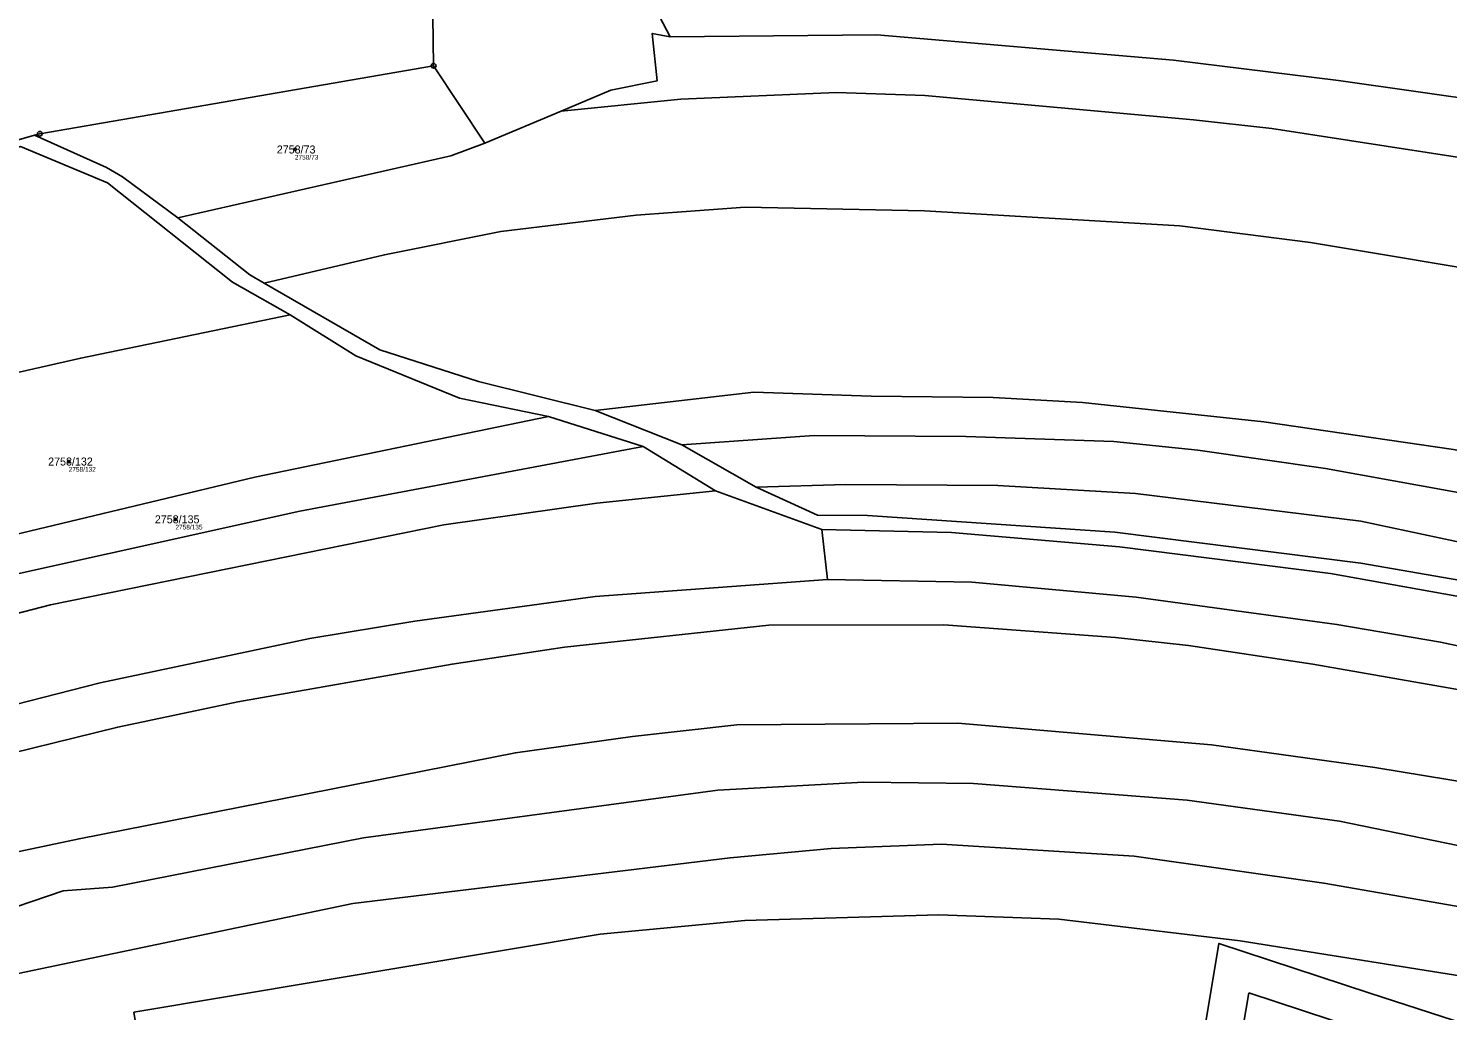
# Model space of a CAD drawing. Extents: x -739214 to -733252, y -1147612 to -1142842.
# Drawn here: x -738866.3 to -738564.8, y -1144790.3 to -1144581.7 of the extents above; entities that cross this region are included whole.
import ezdxf

# ---------------------------------------------------------------- set-up
doc = ezdxf.new("R2010")
doc.units = 0
for name, color, linetype in [('Definiční body', 7, 'Continuous'), ('Hranice parcel', 7, 'Continuous'), ('Parcelní čísla', 7, 'Continuous'), ('Polygon ku', 7, 'Continuous'), ('Polygon parcely', 7, 'Continuous'), ('Věcná břemena k části', 7, 'Continuous'), ('Značky bodu BP', 7, 'Continuous')]:
    doc.layers.add(name, color=color, linetype=linetype)

msp = doc.modelspace()

# ---------------------------------------------------------------- linework, layer by layer
at = {"layer": 'Definiční body'}
for centre in [(-738809.72, -1144607.42), (-738857.77, -1144673.7), (-738835.1, -1144685.97)]:
    msp.add_circle(centre, 0.25, dxfattribs=at)
at = {"layer": 'Hranice parcel'}
for p, q in [((-738780.23, -1144589.65), (-738863.93, -1144604.08)), ((-738769.34, -1144606.08), (-738780.23, -1144589.65)), ((-738769.34, -1144606.08), (-738753.15, -1144599.26)), ((-738863.93, -1144604.08), (-738865.07, -1144604.41)), ((-738755.81, -1144664.17), (-738735.7, -1144670.49)), ((-738727.49, -1144670.14), (-738745.92, -1144662.85)), ((-738735.7, -1144670.49), (-738720.33, -1144679.94)), ((-738711.74, -1144679.15), (-738727.49, -1144670.14)), ((-738720.33, -1144679.94), (-738697.72, -1144688.15)), ((-738697.72, -1144688.15), (-738696.55, -1144698.78))]:
    msp.add_line(p, q, dxfattribs=at)
for points in [[(-738777.14, -1144551.06), (-738777.95, -1144556.74), (-738780.47, -1144573.76), (-738780.23, -1144589.65)], [(-738729.99, -1144583.51), (-738736.86, -1144570.33), (-738742.47, -1144558.02)], [(-738753.15, -1144599.26), (-738742.61, -1144594.82), (-738732.73, -1144592.83), (-738733.79, -1144582.76), (-738729.99, -1144583.51)], [(-738729.99, -1144583.51), (-738686.04, -1144583.08), (-738623, -1144588.46), (-738587.96, -1144592.8), (-738539.21, -1144599.7), (-738494.01, -1144607.59), (-738447.81, -1144618.01), (-738328.4, -1144646.66)], [(-738753.15, -1144599.26), (-738727.73, -1144596.76), (-738694.67, -1144595.34), (-738675.84, -1144595.98), (-738618.78, -1144601.09), (-738602.14, -1144602.93), (-738520.52, -1144615.55), (-738463.61, -1144627.54), (-738400.53, -1144642.44), (-738380.67, -1144646.44), (-738343.35, -1144655.44), (-738326.71, -1144658.87), (-738285.33, -1144666.02)], [(-738865.07, -1144604.41), (-738883.19, -1144609.6), (-738884.82, -1144610.47)], [(-738865.07, -1144604.41), (-738849.74, -1144611.23), (-738846.34, -1144613.24), (-738834.59, -1144621.96)], [(-738884.82, -1144610.47), (-738884.36, -1144611.58), (-738868.01, -1144606.82), (-738849.51, -1144614.5), (-738822.95, -1144635.62), (-738810.74, -1144642.56)], [(-738834.59, -1144621.96), (-738776.55, -1144608.79), (-738769.34, -1144606.08)], [(-738816.27, -1144635.82), (-738790.71, -1144629.78), (-738765.96, -1144624.84), (-738737.19, -1144621.35), (-738714.05, -1144619.69), (-738675.95, -1144620.48), (-738621.71, -1144623.66), (-738593.96, -1144627.15), (-738549.36, -1144634.62), (-738467.05, -1144650.77), (-738381.69, -1144670.37), (-738342.61, -1144677.12), (-738282.28, -1144686.41)], [(-738816.27, -1144635.82), (-738819.32, -1144634.07), (-738834.59, -1144621.96)], [(-738745.92, -1144662.85), (-738770.72, -1144656.73), (-738791.64, -1144649.96), (-738816.27, -1144635.82)], [(-738931.09, -1144668.92), (-738855.23, -1144651.72), (-738810.74, -1144642.56)], [(-738810.74, -1144642.56), (-738796.79, -1144651.27), (-738774.75, -1144660.26), (-738755.81, -1144664.17)], [(-738745.92, -1144662.85), (-738712.17, -1144659), (-738687.27, -1144659.79), (-738661.34, -1144660.12), (-738642.34, -1144661.13), (-738603.83, -1144665.27), (-738563.52, -1144671.15), (-738498, -1144684.06), (-738408.41, -1144703.91), (-738331.12, -1144719.75), (-738279.96, -1144728.46)], [(-738926.48, -1144701.79), (-738906.96, -1144698.24), (-738818.25, -1144677.05), (-738755.81, -1144664.17)], [(-738932.3, -1144703.13), (-738929.68, -1144712.57), (-738889.74, -1144702.21), (-738808.63, -1144684.22), (-738735.7, -1144670.49)], [(-738727.49, -1144670.14), (-738699.4, -1144668.15), (-738667.17, -1144668.37), (-738635.72, -1144669.48), (-738617.89, -1144671.27), (-738590.77, -1144675.16), (-738513.58, -1144689.15), (-738489.83, -1144694.47), (-738438.07, -1144706.79), (-738367.67, -1144721.57), (-738324.91, -1144729.9), (-738281.12, -1144737.92)], [(-739043.64, -1144738.41), (-739021.43, -1144737.54), (-739007.09, -1144735.54), (-738953.36, -1144724.86), (-738895.09, -1144712.74), (-738861.64, -1144704.16), (-738778.06, -1144687.15), (-738745.57, -1144682.54), (-738720.33, -1144679.94)], [(-738711.74, -1144679.15), (-738692.62, -1144678.6), (-738660.39, -1144678.82), (-738631.09, -1144680.49), (-738583.23, -1144686.39), (-738553.27, -1144692.71), (-738520.04, -1144698.71), (-738490.17, -1144704.7), (-738455.52, -1144712.8), (-738414.76, -1144721.93), (-738337.79, -1144737.47), (-738279.92, -1144748.35)], [(-738279.52, -1144758.68), (-738351.8, -1144744.67), (-738450.9, -1144722.85), (-738550.14, -1144701.05), (-738583.22, -1144695.29), (-738635.53, -1144688.73), (-738688.08, -1144685.17), (-738698.64, -1144685.06), (-738711.74, -1144679.15)], [(-738697.72, -1144688.15), (-738670.21, -1144688.75), (-738634.48, -1144691.79), (-738589.69, -1144697.46), (-738544.27, -1144705.61), (-738466.25, -1144723.6), (-738349.01, -1144748.05), (-738333.43, -1144752.01), (-738310.86, -1144756.48), (-738252.1, -1144766.82), (-738206.57, -1144771.52)], [(-738696.55, -1144698.78), (-738745.92, -1144702.39), (-738784.25, -1144707.6), (-738806.51, -1144711.26), (-738851.06, -1144720.74), (-738905.38, -1144734.58), (-738937.68, -1144741.77), (-738989.45, -1144749.94), (-739014.42, -1144755.11), (-739040.71, -1144758.17), (-739064.7, -1144758.63), (-739078.94, -1144757.8), (-739119.14, -1144754.37), (-739143.46, -1144751.76), (-739171.7, -1144747.33)], [(-738696.55, -1144698.78), (-738665.86, -1144699.31), (-738630.96, -1144702.5), (-738588.32, -1144708.29), (-738566.34, -1144712.1), (-738390.66, -1144749.52), (-738318.89, -1144764.13), (-738258.51, -1144774.18), (-738205.92, -1144778.86)], [(-739183.38, -1144756.59), (-739140.87, -1144761.52), (-739094.29, -1144766.15), (-739069.06, -1144767.9), (-739029.63, -1144766.65), (-739012.13, -1144765.04), (-738992.25, -1144760.79), (-738928.27, -1144750.02), (-738847.34, -1144730.12), (-738821.85, -1144724.75), (-738776.3, -1144716.74), (-738752.44, -1144713.11), (-738709, -1144708.48), (-738671.85, -1144708.36), (-738635.33, -1144711.11), (-738619.83, -1144712.74), (-738593.44, -1144716.74), (-738533.1, -1144727.26), (-738443.78, -1144747.77), (-738301.16, -1144775.3), (-738253.9, -1144782.41), (-738204.81, -1144786.85)], [(-739191.93, -1144773.83), (-739136.09, -1144782.62), (-739109.71, -1144785.29), (-739061.67, -1144788.4), (-739035.56, -1144788.05), (-739022.38, -1144787.2), (-738997.38, -1144783.49), (-738951.57, -1144774.09), (-738855.58, -1144753.81), (-738762.86, -1144735.55), (-738738.01, -1144732.08), (-738715.84, -1144729.62), (-738668.84, -1144729.28), (-738614.93, -1144733.9), (-738580.25, -1144738.68), (-738543.66, -1144744.74), (-738483.58, -1144758.77), (-738436.23, -1144768.97), (-738312.61, -1144792.56), (-738198.03, -1144807.72)], [(-739018.23, -1144795.76), (-739001.32, -1144795.15), (-738980.04, -1144791.01), (-738946.98, -1144785.78), (-738875.63, -1144770.55), (-738858.94, -1144764.88), (-738848.45, -1144764.09), (-738795.15, -1144753.65), (-738719.87, -1144743.52), (-738688.88, -1144741.81), (-738665.51, -1144742.12), (-738620.15, -1144745.66), (-738587.73, -1144750.11), (-738403.83, -1144787.9), (-738312.38, -1144804.82), (-738231.13, -1144815.26), (-738195.33, -1144820.56)], [(-739004.88, -1144809.81), (-738937.47, -1144798.69), (-738869.85, -1144782.72), (-738797.38, -1144767.56), (-738717.25, -1144757.85), (-738695.76, -1144755.92), (-738672.31, -1144754.96), (-738631.42, -1144757.49), (-738591.08, -1144763.25), (-738558.06, -1144769.02), (-738499.4, -1144781.27), (-738429.11, -1144797.13), (-738347.02, -1144813.34), (-738244.65, -1144832.1), (-738220.72, -1144837.15)], [(-739010.95, -1144831.34), (-738983.69, -1144828.66), (-738842.39, -1144800.36), (-738843.93, -1144790.67), (-738744.85, -1144774.09), (-738714.09, -1144771.16), (-738672.93, -1144769.95), (-738647.4, -1144770.87), (-738608.88, -1144775.47), (-738559.97, -1144783.32), (-738403.07, -1144818.2), (-738275.19, -1144842.8), (-738222.95, -1144854.1)]]:
    msp.add_lwpolyline(points, dxfattribs=at)
at = {"layer": 'Polygon ku'}
msp.add_lwpolyline([(-738782.62, -1144314.52), (-738764.08, -1144360.02), (-738761.91, -1144378.7), (-738761.22, -1144384.64), (-738769.11, -1144488.57), (-738770.19, -1144501.07), (-738770.52, -1144504.83), (-738777.14, -1144551.06), (-738777.95, -1144556.74), (-738780.47, -1144573.76), (-738780.23, -1144589.65), (-738863.93, -1144604.08), (-738865.07, -1144604.41), (-738883.19, -1144609.6)], dxfattribs=at)
at = {"layer": 'Polygon parcely'}
for points in [[(-738475.09, -1144582.57), (-738550.29, -1144563.03), (-738567.46, -1144567.5), (-738568.5, -1144579.44), (-738625.48, -1144569.7), (-738634.18, -1144556.85), (-738643.91, -1144551.66), (-738653.78, -1144541.27), (-738753.45, -1144529.96), (-738751.26, -1144537.68), (-738742.47, -1144558.02), (-738736.86, -1144570.33), (-738729.99, -1144583.51), (-738686.04, -1144583.08), (-738623, -1144588.46), (-738587.96, -1144592.8), (-738539.21, -1144599.7), (-738494.01, -1144607.59), (-738447.81, -1144618.01), (-738328.4, -1144646.66), (-738337.91, -1144625.79), (-738395.95, -1144612.45), (-738404.05, -1144599.36)], [(-738729.99, -1144583.51), (-738736.86, -1144570.33), (-738742.47, -1144558.02), (-738777.14, -1144551.06), (-738777.95, -1144556.74), (-738780.47, -1144573.76), (-738780.23, -1144589.65), (-738769.34, -1144606.08), (-738753.15, -1144599.26), (-738742.61, -1144594.82), (-738732.73, -1144592.83), (-738733.79, -1144582.76)], [(-738834.59, -1144621.96), (-738776.55, -1144608.79), (-738769.34, -1144606.08), (-738780.23, -1144589.65), (-738863.93, -1144604.08), (-738865.07, -1144604.41), (-738849.74, -1144611.23), (-738846.34, -1144613.24)], [(-738931.09, -1144668.92), (-738855.23, -1144651.72), (-738810.74, -1144642.56), (-738822.95, -1144635.62), (-738849.51, -1144614.5), (-738868.01, -1144606.82), (-738884.36, -1144611.58), (-738884.82, -1144610.47), (-738920.58, -1144629.59), (-738941.79, -1144651.66), (-738967.26, -1144676.45)], [(-738926.48, -1144701.79), (-738906.96, -1144698.24), (-738818.25, -1144677.05), (-738755.81, -1144664.17), (-738774.75, -1144660.26), (-738796.79, -1144651.27), (-738810.74, -1144642.56), (-738855.23, -1144651.72), (-738931.09, -1144668.92), (-738929.55, -1144677.06), (-738928.17, -1144695.03)], [(-738281.12, -1144737.92), (-738279.96, -1144728.46), (-738331.12, -1144719.75), (-738408.41, -1144703.91), (-738498, -1144684.06), (-738563.52, -1144671.15), (-738603.83, -1144665.27), (-738642.34, -1144661.13), (-738661.34, -1144660.12), (-738687.27, -1144659.79), (-738712.17, -1144659), (-738745.92, -1144662.85), (-738727.49, -1144670.14), (-738699.4, -1144668.15), (-738667.17, -1144668.37), (-738635.72, -1144669.48), (-738617.89, -1144671.27), (-738590.77, -1144675.16), (-738513.58, -1144689.15), (-738489.83, -1144694.47), (-738438.07, -1144706.79), (-738367.67, -1144721.57), (-738324.91, -1144729.9)], [(-738889.74, -1144702.21), (-738808.63, -1144684.22), (-738735.7, -1144670.49), (-738755.81, -1144664.17), (-738818.25, -1144677.05), (-738906.96, -1144698.24), (-738926.48, -1144701.79), (-738932.3, -1144703.13), (-738929.68, -1144712.57)], [(-739021.43, -1144737.54), (-739007.09, -1144735.54), (-738953.36, -1144724.86), (-738895.09, -1144712.74), (-738861.64, -1144704.16), (-738778.06, -1144687.15), (-738745.57, -1144682.54), (-738720.33, -1144679.94), (-738735.7, -1144670.49), (-738808.63, -1144684.22), (-738889.74, -1144702.21), (-738929.68, -1144712.57), (-738932.3, -1144703.13), (-738975.23, -1144713.01), (-739014.09, -1144719.06), (-739014.33, -1144725.67), (-739043.39, -1144730.93), (-739043.64, -1144738.41)], [(-738660.39, -1144678.82), (-738631.09, -1144680.49), (-738583.23, -1144686.39), (-738553.27, -1144692.71), (-738520.04, -1144698.71), (-738490.17, -1144704.7), (-738455.52, -1144712.8), (-738414.76, -1144721.93), (-738337.79, -1144737.47), (-738279.92, -1144748.35), (-738281.12, -1144737.92), (-738324.91, -1144729.9), (-738367.67, -1144721.57), (-738438.07, -1144706.79), (-738489.83, -1144694.47), (-738513.58, -1144689.15), (-738590.77, -1144675.16), (-738617.89, -1144671.27), (-738635.72, -1144669.48), (-738667.17, -1144668.37), (-738699.4, -1144668.15), (-738727.49, -1144670.14), (-738711.74, -1144679.15), (-738692.62, -1144678.6)], [(-738711.74, -1144679.15), (-738698.64, -1144685.06), (-738688.08, -1144685.17), (-738635.53, -1144688.73), (-738583.22, -1144695.29), (-738550.14, -1144701.05), (-738450.9, -1144722.85), (-738351.8, -1144744.67), (-738279.52, -1144758.68), (-738279.92, -1144748.35), (-738337.79, -1144737.47), (-738414.76, -1144721.93), (-738455.52, -1144712.8), (-738490.17, -1144704.7), (-738520.04, -1144698.71), (-738553.27, -1144692.71), (-738583.23, -1144686.39), (-738631.09, -1144680.49), (-738660.39, -1144678.82), (-738692.62, -1144678.6)], [(-738665.86, -1144699.31), (-738630.96, -1144702.5), (-738588.32, -1144708.29), (-738566.34, -1144712.1), (-738390.66, -1144749.52), (-738318.89, -1144764.13), (-738258.51, -1144774.18), (-738205.92, -1144778.86), (-738206.57, -1144771.52), (-738252.1, -1144766.82), (-738310.86, -1144756.48), (-738333.43, -1144752.01), (-738349.01, -1144748.05), (-738466.25, -1144723.6), (-738544.27, -1144705.61), (-738589.69, -1144697.46), (-738634.48, -1144691.79), (-738670.21, -1144688.75), (-738697.72, -1144688.15), (-738696.55, -1144698.78)]]:
    msp.add_lwpolyline(points, close=True, dxfattribs=at)
for points in [[(-738539.21, -1144599.7), (-738587.96, -1144592.8), (-738623, -1144588.46), (-738686.04, -1144583.08), (-738729.99, -1144583.51), (-738733.79, -1144582.76), (-738732.73, -1144592.83), (-738742.61, -1144594.82), (-738753.15, -1144599.26), (-738727.73, -1144596.76), (-738694.67, -1144595.34), (-738675.84, -1144595.98), (-738618.78, -1144601.09), (-738602.14, -1144602.93), (-738520.52, -1144615.55)], [(-738520.52, -1144615.55), (-738602.14, -1144602.93), (-738618.78, -1144601.09), (-738675.84, -1144595.98), (-738694.67, -1144595.34), (-738727.73, -1144596.76), (-738753.15, -1144599.26), (-738769.34, -1144606.08), (-738776.55, -1144608.79), (-738834.59, -1144621.96), (-738819.32, -1144634.07), (-738816.27, -1144635.82), (-738790.71, -1144629.78), (-738765.96, -1144624.84), (-738737.19, -1144621.35), (-738714.05, -1144619.69), (-738675.95, -1144620.48), (-738621.71, -1144623.66), (-738593.96, -1144627.15), (-738549.36, -1144634.62)], [(-738173.15, -1144741.66), (-738178.08, -1144745.11), (-738204.12, -1144760.48), (-738215.71, -1144765.89), (-738279.52, -1144758.68), (-738351.8, -1144744.67), (-738450.9, -1144722.85), (-738550.14, -1144701.05), (-738583.22, -1144695.29), (-738635.53, -1144688.73), (-738688.08, -1144685.17), (-738698.64, -1144685.06), (-738711.74, -1144679.15), (-738727.49, -1144670.14), (-738745.92, -1144662.85), (-738770.72, -1144656.73), (-738791.64, -1144649.96), (-738816.27, -1144635.82), (-738819.32, -1144634.07), (-738834.59, -1144621.96), (-738846.34, -1144613.24), (-738849.74, -1144611.23), (-738865.07, -1144604.41), (-738883.19, -1144609.6)], [(-738868.01, -1144606.82), (-738849.51, -1144614.5), (-738822.95, -1144635.62), (-738810.74, -1144642.56), (-738796.79, -1144651.27), (-738774.75, -1144660.26), (-738755.81, -1144664.17), (-738735.7, -1144670.49), (-738720.33, -1144679.94), (-738697.72, -1144688.15), (-738670.21, -1144688.75), (-738634.48, -1144691.79), (-738589.69, -1144697.46), (-738544.27, -1144705.61), (-738466.25, -1144723.6), (-738349.01, -1144748.05), (-738333.43, -1144752.01), (-738310.86, -1144756.48), (-738252.1, -1144766.82), (-738206.57, -1144771.52), (-738202.28, -1144772.1), (-738203.02, -1144765.99), (-738191.17, -1144759.44), (-738166.35, -1144745.34)], [(-738549.36, -1144634.62), (-738593.96, -1144627.15), (-738621.71, -1144623.66), (-738675.95, -1144620.48), (-738714.05, -1144619.69), (-738737.19, -1144621.35), (-738765.96, -1144624.84), (-738790.71, -1144629.78), (-738816.27, -1144635.82), (-738791.64, -1144649.96), (-738770.72, -1144656.73), (-738745.92, -1144662.85), (-738712.17, -1144659), (-738687.27, -1144659.79), (-738661.34, -1144660.12), (-738642.34, -1144661.13), (-738603.83, -1144665.27), (-738563.52, -1144671.15)], [(-738905.38, -1144734.58), (-738851.06, -1144720.74), (-738806.51, -1144711.26), (-738784.25, -1144707.6), (-738745.92, -1144702.39), (-738696.55, -1144698.78), (-738697.72, -1144688.15), (-738720.33, -1144679.94), (-738745.57, -1144682.54), (-738778.06, -1144687.15), (-738861.64, -1144704.16), (-738895.09, -1144712.74)], [(-738390.66, -1144749.52), (-738566.34, -1144712.1), (-738588.32, -1144708.29), (-738630.96, -1144702.5), (-738665.86, -1144699.31), (-738696.55, -1144698.78), (-738745.92, -1144702.39), (-738784.25, -1144707.6), (-738806.51, -1144711.26), (-738851.06, -1144720.74), (-738905.38, -1144734.58)], [(-738928.27, -1144750.02), (-738847.34, -1144730.12), (-738821.85, -1144724.75), (-738776.3, -1144716.74), (-738752.44, -1144713.11), (-738709, -1144708.48), (-738671.85, -1144708.36), (-738635.33, -1144711.11), (-738619.83, -1144712.74), (-738593.44, -1144716.74), (-738533.1, -1144727.26)], [(-738533.1, -1144727.26), (-738593.44, -1144716.74), (-738619.83, -1144712.74), (-738635.33, -1144711.11), (-738671.85, -1144708.36), (-738709, -1144708.48), (-738752.44, -1144713.11), (-738776.3, -1144716.74), (-738821.85, -1144724.75), (-738847.34, -1144730.12), (-738928.27, -1144750.02)], [(-738951.57, -1144774.09), (-738855.58, -1144753.81), (-738762.86, -1144735.55), (-738738.01, -1144732.08), (-738715.84, -1144729.62), (-738668.84, -1144729.28), (-738614.93, -1144733.9), (-738580.25, -1144738.68), (-738543.66, -1144744.74)], [(-738543.66, -1144744.74), (-738580.25, -1144738.68), (-738614.93, -1144733.9), (-738668.84, -1144729.28), (-738715.84, -1144729.62), (-738738.01, -1144732.08), (-738762.86, -1144735.55), (-738855.58, -1144753.81), (-738951.57, -1144774.09)], [(-738875.63, -1144770.55), (-738858.94, -1144764.88), (-738848.45, -1144764.09), (-738795.15, -1144753.65), (-738719.87, -1144743.52), (-738688.88, -1144741.81), (-738665.51, -1144742.12), (-738620.15, -1144745.66), (-738587.73, -1144750.11), (-738403.83, -1144787.9)], [(-738403.83, -1144787.9), (-738587.73, -1144750.11), (-738620.15, -1144745.66), (-738665.51, -1144742.12), (-738688.88, -1144741.81), (-738719.87, -1144743.52), (-738795.15, -1144753.65), (-738848.45, -1144764.09), (-738858.94, -1144764.88), (-738875.63, -1144770.55)], [(-738869.85, -1144782.72), (-738797.38, -1144767.56), (-738717.25, -1144757.85), (-738695.76, -1144755.92), (-738672.31, -1144754.96), (-738631.42, -1144757.49), (-738591.08, -1144763.25), (-738558.06, -1144769.02)], [(-738558.06, -1144769.02), (-738591.08, -1144763.25), (-738631.42, -1144757.49), (-738672.31, -1144754.96), (-738695.76, -1144755.92), (-738717.25, -1144757.85), (-738797.38, -1144767.56), (-738869.85, -1144782.72)], [(-738983.69, -1144828.66), (-738842.39, -1144800.36), (-738843.93, -1144790.67), (-738744.85, -1144774.09), (-738714.09, -1144771.16), (-738672.93, -1144769.95), (-738647.4, -1144770.87), (-738608.88, -1144775.47), (-738559.97, -1144783.32)], [(-738559.97, -1144783.32), (-738608.88, -1144775.47), (-738647.4, -1144770.87), (-738672.93, -1144769.95), (-738714.09, -1144771.16), (-738744.85, -1144774.09), (-738843.93, -1144790.67), (-738842.39, -1144800.36), (-738983.69, -1144828.66)]]:
    msp.add_lwpolyline(points, dxfattribs=at)
at = {"layer": 'Věcná břemena k části'}
msp.add_lwpolyline([(-738607.04, -1144786.57), (-738583.77, -1144794.22), (-738548.1, -1144805.77), (-738513.77, -1144816.67), (-738508.97, -1144817.73), (-738452.34, -1144832.16), (-738417.69, -1144839.34), (-738425.94, -1144836.65), (-738461.79, -1144824.81), (-738510.24, -1144809.4), (-738545.66, -1144798.15), (-738581.29, -1144786.62), (-738613.4, -1144776.07), (-738616.96, -1144797.36), (-738608.99, -1144798.23)], close=True, dxfattribs=at)
at = {"layer": 'Značky bodu BP'}
for centre, radius in [((-738780.23, -1144589.65), 0.5), ((-738780.23, -1144589.65), 0.0303), ((-738863.93, -1144604.08), 0.5), ((-738863.93, -1144604.08), 0.0303)]:
    msp.add_circle(centre, radius, dxfattribs=at)

# ---------------------------------------------------------------- texts
at = {"layer": 'Definiční body'}
for s, p in [('2758/73', (-738809.72, -1144609.58)), ('2758/132', (-738857.77, -1144675.86)), ('2758/135', (-738835.1, -1144688.13))]:
    msp.add_text(s, height=1, dxfattribs=at).set_placement(p)
at = {"layer": 'Parcelní čísla'}
for s, p in [('2758/73', (-738813.56, -1144608.27)), ('2758/132', (-738862.14, -1144674.55)), ('2758/135', (-738839.47, -1144686.82))]:
    msp.add_text(s, height=1.7, dxfattribs=at).set_placement(p)

doc.saveas('drawing.dxf')
